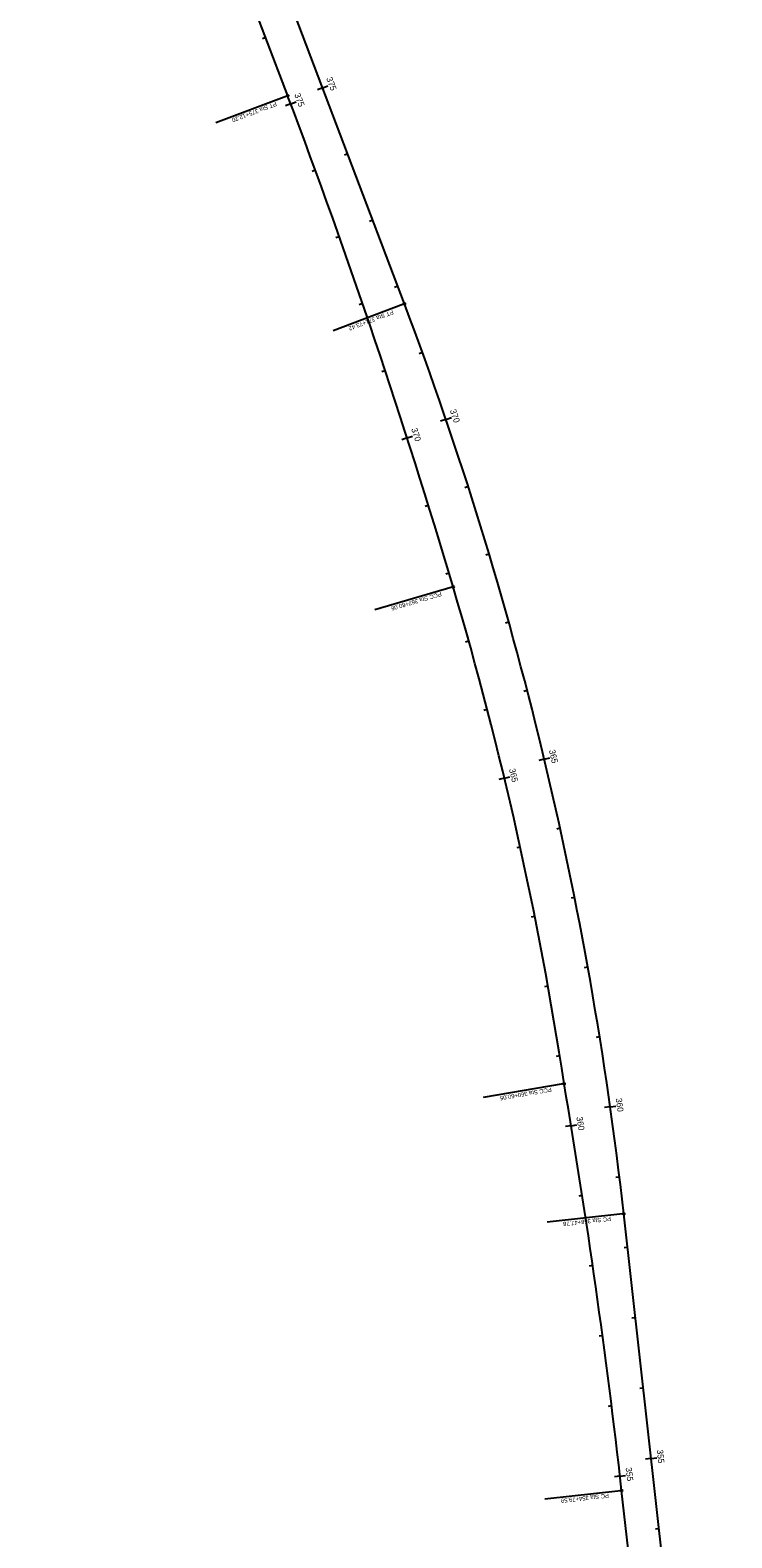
# Model space of a CAD drawing. Extents: x 1602163 to 1612907, y 1087635 to 1096265.
# Drawn here: x 1611542 to 1612534, y 1089807 to 1091937 of the extents above; entities that cross this region are included whole.
import ezdxf

# ---------------------------------------------------------------- set-up
doc = ezdxf.new("R2010")
doc.units = 0
for name, color, linetype in [('RD_HC_Cl', 7, 'Continuous'), ('RD_HC_Data_Tic', 7, 'Continuous'), ('RD_HC_Points', 7, 'Continuous'), ('RD_HC_TX_Sta50', 7, 'Continuous')]:
    doc.layers.add(name, color=color, linetype=linetype)

msp = doc.modelspace()

# ---------------------------------------------------------------- linework, layer by layer
at = {"layer": 'RD_HC_Cl'}
for p, q in [((1611906.2, 1091844.6), (1611542.3, 1092806.5)), ((1612071.1, 1091550.5), (1611593.4, 1092813.6)), ((1612533.6, 1088900.6), (1612380.9, 1090265.1)), ((1612487.4, 1088895.4), (1612377.9, 1089874.1))]:
    msp.add_line(p, q, dxfattribs=at)
for centre, radius, start, end in [((1602552.7, 1088307.1), 10000, 16.52176, 20.71665), ((1607113.8, 1089675.6), 5300, 6.3858, 20.7167), ((1607115.5, 1089660.5), 5240.8, 8.6501, 16.5218), ((1602439.9, 1088761.9), 10000, 6.3858, 9.71157)]:
    msp.add_arc(centre, radius, start, end, dxfattribs=at)
at = {"layer": 'RD_HC_Data_Tic'}
for p, q in [((1611875.1, 1091926.7), (1611870.4, 1091924.9)), ((1611955.6, 1091855.9), (1611948.1, 1091853.1)), ((1611955.6, 1091855.9), (1611963.1, 1091858.7)), ((1611910.5, 1091833.2), (1611903, 1091830.3)), ((1611910.5, 1091833.2), (1611918, 1091836)), ((1611991, 1091762.4), (1611986.3, 1091760.6)), ((1611945.3, 1091739.4), (1611940.6, 1091737.7)), ((1612026.3, 1091668.9), (1612021.7, 1091667.1)), ((1611979.1, 1091645.3), (1611974.4, 1091643.6)), ((1612061.7, 1091575.3), (1612057, 1091573.5)), ((1612012, 1091550.9), (1612007.3, 1091549.3)), ((1612096.6, 1091481.6), (1612091.9, 1091479.9)), ((1612044, 1091456.1), (1612039.2, 1091454.6)), ((1612129.8, 1091387.3), (1612122.2, 1091384.7)), ((1612129.8, 1091387.3), (1612137.4, 1091389.9)), ((1612075, 1091361.1), (1612067.4, 1091358.6)), ((1612075, 1091361.1), (1612082.6, 1091363.5)), ((1612161.2, 1091292.3), (1612156.4, 1091290.8)), ((1612105.1, 1091265.7), (1612100.3, 1091264.2)), ((1612190.8, 1091196.8), (1612186, 1091195.4)), ((1612134.2, 1091170), (1612129.4, 1091168.6)), ((1612218.6, 1091100.8), (1612213.8, 1091099.4)), ((1612162, 1091074), (1612157.2, 1091072.6)), ((1612244.6, 1091004.2), (1612239.7, 1091002.9)), ((1612188.1, 1090977.4), (1612183.3, 1090976.2)), ((1612268.7, 1090907.2), (1612261, 1090905.3)), ((1612268.7, 1090907.2), (1612276.5, 1090909)), ((1612212.3, 1090880.4), (1612204.5, 1090878.5)), ((1612212.3, 1090880.4), (1612220.1, 1090882.3)), ((1612291.1, 1090809.7), (1612286.2, 1090808.6)), ((1612234.6, 1090782.9), (1612229.8, 1090781.9)), ((1612311.5, 1090711.8), (1612306.6, 1090710.8)), ((1612255.1, 1090685.1), (1612250.2, 1090684.1)), ((1612330.2, 1090613.6), (1612325.2, 1090612.7)), ((1612273.7, 1090586.8), (1612268.8, 1090585.9)), ((1612346.9, 1090515), (1612342, 1090514.2)), ((1612290.5, 1090488.2), (1612285.5, 1090487.4)), ((1612361.8, 1090416.1), (1612353.9, 1090415)), ((1612361.8, 1090416.1), (1612369.8, 1090417.2)), ((1612306.6, 1090389.5), (1612298.7, 1090388.2)), ((1612306.6, 1090389.5), (1612314.5, 1090390.8)), ((1612374.9, 1090316.9), (1612369.9, 1090316.3)), ((1612322.4, 1090290.8), (1612317.4, 1090290)), ((1612386.2, 1090217.6), (1612381.3, 1090217)), ((1612337.2, 1090191.9), (1612332.2, 1090191.2)), ((1612397.4, 1090118.2), (1612392.4, 1090117.7)), ((1612351, 1090092.8), (1612346, 1090092.2)), ((1612408.5, 1090018.8), (1612403.5, 1090018.3)), ((1612363.8, 1089993.7), (1612358.8, 1089993)), ((1612419.6, 1089919.5), (1612411.7, 1089918.6)), ((1612419.6, 1089919.5), (1612427.6, 1089920.3)), ((1612375.6, 1089894.4), (1612367.7, 1089893.5)), ((1612375.6, 1089894.4), (1612383.6, 1089895.3)), ((1612430.7, 1089820.1), (1612425.8, 1089819.5))]:
    msp.add_line(p, q, dxfattribs=at)
at = {"layer": 'RD_HC_Points'}
for p, q in [((1611905, 1091844.1), (1611804.7, 1091806.2)), ((1612070, 1091550), (1611970.5, 1091512.4)), ((1612138.7, 1091150.5), (1612029.4, 1091118.1)), ((1612295.4, 1090448.5), (1612182.2, 1090429.2)), ((1612379.7, 1090264.9), (1612272.8, 1090253)), ((1612376.7, 1089873.9), (1612269.3, 1089861.9))]:
    msp.add_line(p, q, dxfattribs=at)
for centre in [(1611906.2, 1091844.6), (1612071.1, 1091550.5), (1612139.9, 1091150.9), (1612296.6, 1090448.7), (1612380.9, 1090265.1), (1612377.9, 1089874.1)]:
    msp.add_circle(centre, 1.25, dxfattribs=at)

# ---------------------------------------------------------------- texts
for s, rotation, p in [('PT Sta 375+12.20', 200.7167, (1611889.3, 1091836.1)), ('PT Sta 371+73.42', 200.7167, (1612054.3, 1091541.9)), ('PCC Sta 367+80.06', 196.5218, (1612122.5, 1091143.7)), ('PCC Sta 360+60.05', 189.7116, (1612278.5, 1090443.6)), ('PC Sta 358+47.78', 186.3858, (1612362.5, 1090261)), ('PC Sta 354+79.59', 186.3858, (1612359.5, 1089870))]:
    msp.add_text(s, height=6, rotation=rotation, dxfattribs=at).set_placement(p)
at = {"layer": 'RD_HC_TX_Sta50'}
for s, rotation, p in [('375', 290.7167, (1611960.5, 1091869)), ('375', 290.6467, (1611915.4, 1091846.2)), ('370', 288.8419, (1612135.2, 1091400.1)), ('370', 287.7819, (1612080.6, 1091373.8)), ('365', 283.4367, (1612275.2, 1090919.7)), ('365', 283.46, (1612218.8, 1090893)), ('360', 278.0314, (1612369.5, 1090427.9)), ('360', 279.3675, (1612314, 1090401.5)), ('355', 276.3858, (1612427.6, 1089931.4)), ('355', 276.5027, (1612383.6, 1089906.3))]:
    msp.add_text(s, height=8.75, rotation=rotation, dxfattribs=at).set_placement(p)

doc.saveas('drawing.dxf')
